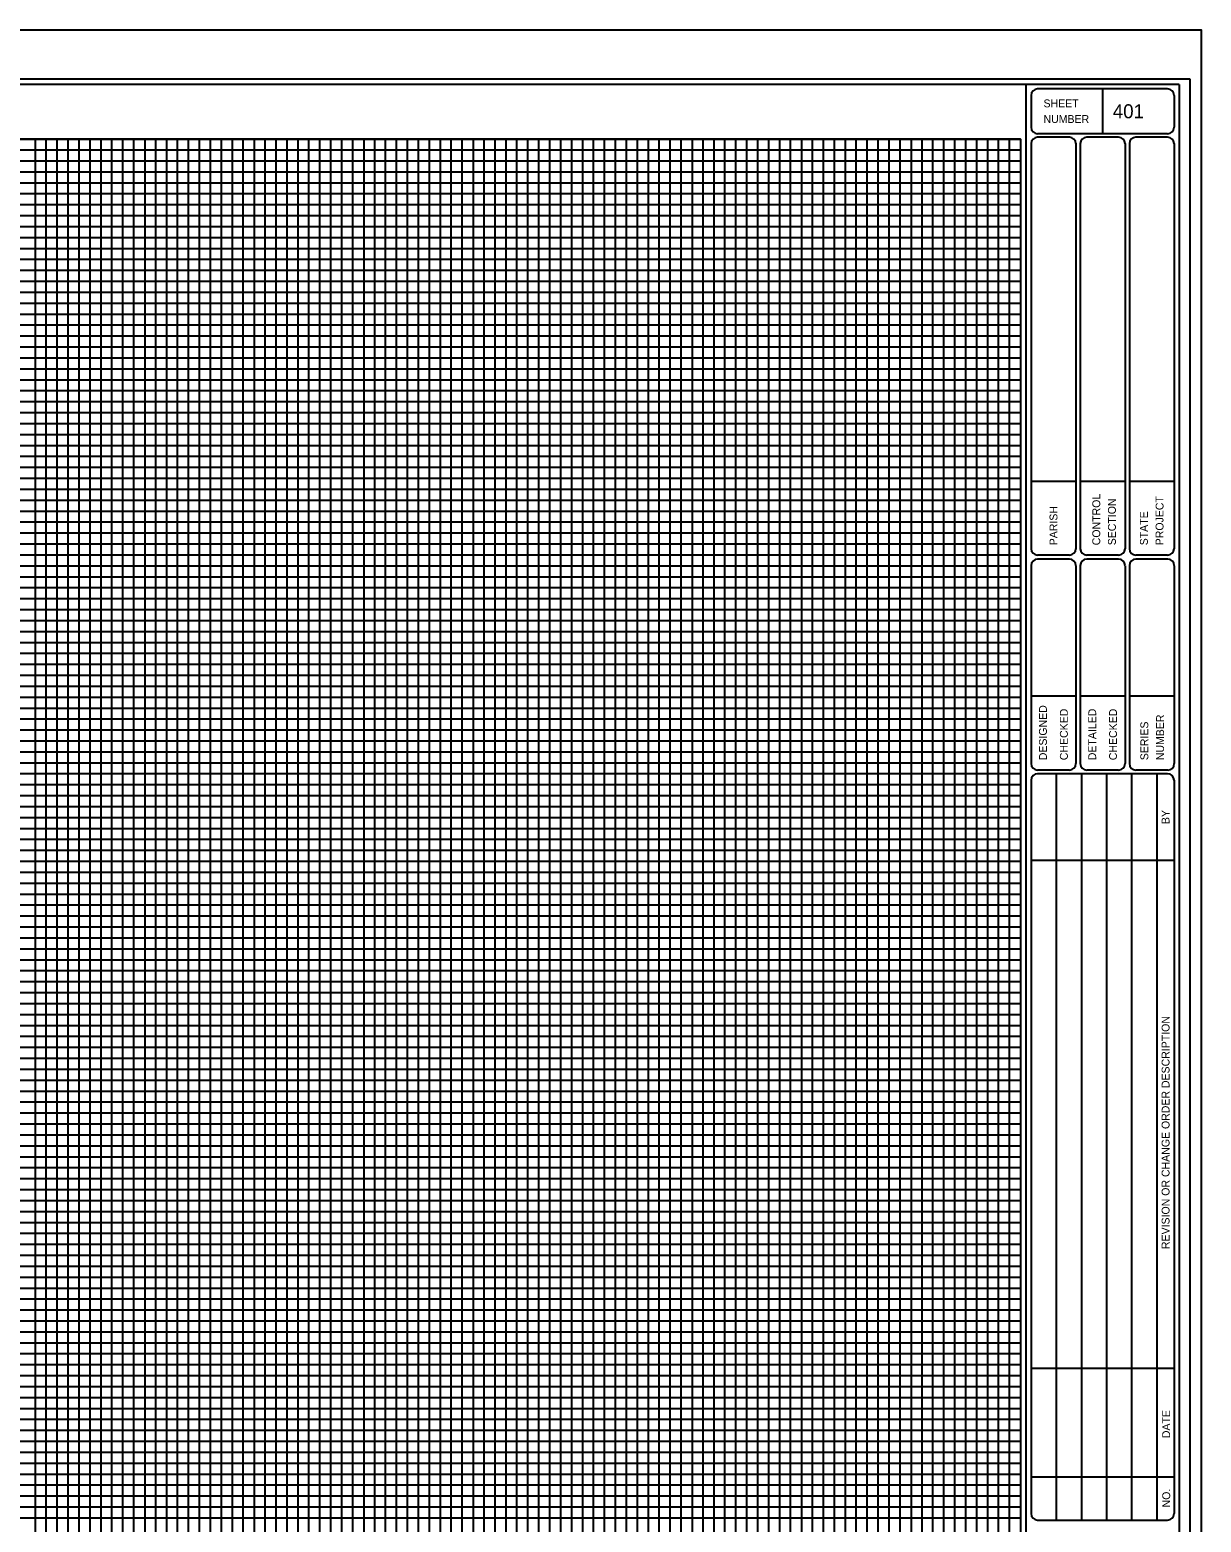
# Model space of a CAD drawing. Extents: x -139 to 18809, y -75 to 270.
# Drawn here: x 233 to 340, y 83.6 to 220 of the extents above; entities that cross this region are included whole.
import ezdxf

# ---------------------------------------------------------------- set-up
doc = ezdxf.new("R2010")
doc.units = 0
for name, color, linetype in [('Grid', 7, 'Continuous'), ('Plot Border', 7, 'Continuous'), ('Sheet Border', 7, 'Continuous')]:
    doc.layers.add(name, color=color, linetype=linetype)

msp = doc.modelspace()

# ---------------------------------------------------------------- linework, layer by layer
at = {"layer": 'Grid'}
for p, q in [((323.5, 210), (23.5, 210)), ((323.5, 209), (23.5, 209)), ((233.5, 210), (233.5, 10)), ((234.5, 10), (234.5, 210)), ((235.5, 10), (235.5, 210)), ((236.5, 10), (236.5, 210)), ((237.5, 10), (237.5, 210)), ((238.5, 10), (238.5, 210)), ((239.5, 10), (239.5, 210)), ((240.5, 10), (240.5, 210)), ((241.5, 10), (241.5, 210)), ((242.5, 10), (242.5, 210)), ((243.5, 210), (243.5, 10)), ((244.5, 10), (244.5, 210)), ((245.5, 10), (245.5, 210)), ((246.5, 10), (246.5, 210)), ((247.5, 10), (247.5, 210)), ((248.5, 10), (248.5, 210)), ((249.5, 10), (249.5, 210)), ((250.5, 10), (250.5, 210)), ((251.5, 10), (251.5, 210)), ((252.5, 10), (252.5, 210)), ((253.5, 210), (253.5, 10)), ((254.5, 10), (254.5, 210)), ((255.5, 10), (255.5, 210)), ((256.5, 10), (256.5, 210)), ((257.5, 10), (257.5, 210)), ((258.5, 10), (258.5, 210)), ((259.5, 10), (259.5, 210)), ((260.5, 10), (260.5, 210)), ((261.5, 10), (261.5, 210)), ((262.5, 10), (262.5, 210)), ((263.5, 210), (263.5, 10)), ((264.5, 10), (264.5, 210)), ((265.5, 10), (265.5, 210)), ((266.5, 10), (266.5, 210)), ((267.5, 10), (267.5, 210)), ((268.5, 10), (268.5, 210)), ((269.5, 10), (269.5, 210)), ((270.5, 10), (270.5, 210)), ((271.5, 10), (271.5, 210)), ((272.5, 10), (272.5, 210)), ((273.5, 210), (273.5, 10)), ((274.5, 10), (274.5, 210)), ((275.5, 10), (275.5, 210)), ((276.5, 10), (276.5, 210)), ((277.5, 10), (277.5, 210)), ((278.5, 10), (278.5, 210)), ((279.5, 10), (279.5, 210)), ((280.5, 10), (280.5, 210)), ((281.5, 10), (281.5, 210)), ((282.5, 10), (282.5, 210)), ((283.5, 210), (283.5, 10)), ((284.5, 10), (284.5, 210)), ((285.5, 10), (285.5, 210)), ((286.5, 10), (286.5, 210)), ((287.5, 10), (287.5, 210)), ((288.5, 10), (288.5, 210)), ((289.5, 10), (289.5, 210)), ((290.5, 10), (290.5, 210)), ((291.5, 10), (291.5, 210)), ((292.5, 10), (292.5, 210)), ((293.5, 210), (293.5, 10)), ((294.5, 10), (294.5, 210)), ((295.5, 10), (295.5, 210)), ((296.5, 10), (296.5, 210)), ((297.5, 10), (297.5, 210)), ((298.5, 10), (298.5, 210)), ((299.5, 10), (299.5, 210)), ((300.5, 10), (300.5, 210)), ((301.5, 10), (301.5, 210)), ((302.5, 10), (302.5, 210)), ((303.5, 210), (303.5, 10)), ((304.5, 10), (304.5, 210)), ((305.5, 10), (305.5, 210)), ((306.5, 10), (306.5, 210)), ((307.5, 10), (307.5, 210)), ((308.5, 10), (308.5, 210)), ((309.5, 10), (309.5, 210)), ((310.5, 10), (310.5, 210)), ((311.5, 10), (311.5, 210)), ((312.5, 10), (312.5, 210)), ((313.5, 210), (313.5, 10)), ((314.5, 10), (314.5, 210)), ((315.5, 10), (315.5, 210)), ((316.5, 10), (316.5, 210)), ((317.5, 10), (317.5, 210)), ((318.5, 10), (318.5, 210)), ((319.5, 10), (319.5, 210)), ((320.5, 10), (320.5, 210)), ((321.5, 10), (321.5, 210)), ((322.5, 10), (322.5, 210)), ((323.5, 208), (23.5, 208)), ((323.5, 207), (23.5, 207)), ((323.5, 206), (23.5, 206)), ((323.5, 205), (23.5, 205)), ((323.5, 204), (23.5, 204)), ((323.5, 203), (23.5, 203)), ((323.5, 202), (23.5, 202)), ((323.5, 201), (23.5, 201)), ((323.5, 200), (23.5, 200)), ((323.5, 199), (23.5, 199)), ((323.5, 198), (23.5, 198)), ((323.5, 197), (23.5, 197)), ((323.5, 196), (23.5, 196)), ((323.5, 195), (23.5, 195)), ((323.5, 194), (23.5, 194)), ((323.5, 193), (23.5, 193)), ((323.5, 192), (23.5, 192)), ((323.5, 191), (23.5, 191)), ((323.5, 190), (23.5, 190)), ((323.5, 189), (23.5, 189)), ((323.5, 188), (23.5, 188)), ((323.5, 187), (23.5, 187)), ((323.5, 186), (23.5, 186)), ((323.5, 185), (23.5, 185)), ((323.5, 184), (23.5, 184)), ((323.5, 183), (23.5, 183)), ((323.5, 182), (23.5, 182)), ((323.5, 181), (23.5, 181)), ((323.5, 180), (23.5, 180)), ((323.5, 179), (23.5, 179)), ((323.5, 178), (23.5, 178)), ((323.5, 177), (23.5, 177)), ((323.5, 176), (23.5, 176)), ((323.5, 175), (23.5, 175)), ((323.5, 174), (23.5, 174)), ((323.5, 173), (23.5, 173)), ((323.5, 172), (23.5, 172)), ((323.5, 171), (23.5, 171)), ((323.5, 170), (23.5, 170)), ((323.5, 169), (23.5, 169)), ((323.5, 168), (23.5, 168)), ((323.5, 167), (23.5, 167)), ((323.5, 166), (23.5, 166)), ((323.5, 165), (23.5, 165)), ((323.5, 164), (23.5, 164)), ((323.5, 163), (23.5, 163)), ((323.5, 162), (23.5, 162)), ((323.5, 161), (23.5, 161)), ((323.5, 160), (23.5, 160)), ((323.5, 159), (23.5, 159)), ((323.5, 158), (23.5, 158)), ((323.5, 157), (23.5, 157)), ((323.5, 156), (23.5, 156)), ((323.5, 155), (23.5, 155)), ((323.5, 154), (23.5, 154)), ((323.5, 153), (23.5, 153)), ((323.5, 152), (23.5, 152)), ((323.5, 151), (23.5, 151)), ((323.5, 150), (23.5, 150)), ((323.5, 149), (23.5, 149)), ((323.5, 148), (23.5, 148)), ((323.5, 147), (23.5, 147)), ((323.5, 146), (23.5, 146)), ((323.5, 145), (23.5, 145)), ((323.5, 144), (23.5, 144)), ((323.5, 143), (23.5, 143)), ((323.5, 142), (23.5, 142)), ((323.5, 141), (23.5, 141)), ((323.5, 140), (23.5, 140)), ((323.5, 139), (23.5, 139)), ((323.5, 138), (23.5, 138)), ((323.5, 137), (23.5, 137)), ((323.5, 136), (23.5, 136)), ((323.5, 135), (23.5, 135)), ((323.5, 134), (23.5, 134)), ((323.5, 133), (23.5, 133)), ((323.5, 132), (23.5, 132)), ((323.5, 131), (23.5, 131)), ((323.5, 130), (23.5, 130)), ((323.5, 129), (23.5, 129)), ((323.5, 128), (23.5, 128)), ((323.5, 127), (23.5, 127)), ((323.5, 126), (23.5, 126)), ((323.5, 125), (23.5, 125)), ((323.5, 124), (23.5, 124)), ((323.5, 123), (23.5, 123)), ((323.5, 122), (23.5, 122)), ((323.5, 121), (23.5, 121)), ((323.5, 120), (23.5, 120)), ((323.5, 119), (23.5, 119)), ((323.5, 118), (23.5, 118)), ((323.5, 117), (23.5, 117)), ((323.5, 116), (23.5, 116)), ((323.5, 115), (23.5, 115)), ((323.5, 114), (23.5, 114)), ((323.5, 113), (23.5, 113)), ((323.5, 112), (23.5, 112)), ((323.5, 111), (23.5, 111)), ((323.5, 110), (23.5, 110)), ((323.5, 109), (23.5, 109)), ((323.5, 108), (23.5, 108)), ((323.5, 107), (23.5, 107)), ((323.5, 106), (23.5, 106)), ((323.5, 105), (23.5, 105)), ((323.5, 104), (23.5, 104)), ((323.5, 103), (23.5, 103)), ((323.5, 102), (23.5, 102)), ((323.5, 101), (23.5, 101)), ((323.5, 100), (23.5, 100)), ((323.5, 99), (23.5, 99)), ((323.5, 98), (23.5, 98)), ((323.5, 97), (23.5, 97)), ((323.5, 96), (23.5, 96)), ((323.5, 95), (23.5, 95)), ((323.5, 94), (23.5, 94)), ((323.5, 93), (23.5, 93)), ((323.5, 92), (23.5, 92)), ((323.5, 91), (23.5, 91)), ((323.5, 90), (23.5, 90)), ((323.5, 89), (23.5, 89)), ((323.5, 88), (23.5, 88)), ((323.5, 87), (23.5, 87)), ((323.5, 86), (23.5, 86)), ((323.5, 85), (23.5, 85)), ((323.5, 84), (23.5, 84))]:
    msp.add_line(p, q, dxfattribs=at)
msp.add_lwpolyline([(23.5, 210), (323.5, 210), (323.5, 10), (23.5, 10)], close=True, dxfattribs=at)
at = {"layer": 'Plot Border'}
for points in [[(0, 220), (340, 220), (340, 0), (0, 0)], [(339, 215.5), (9, 215.5), (9, 4.5), (339, 4.5)]]:
    msp.add_lwpolyline(points, close=True, dxfattribs=at)
at = {"layer": 'Sheet Border'}
for p, q in [((338, 215), (23, 215)), ((324, 215), (324, 5)), ((336.94, 214.6), (325.06, 214.6)), ((331, 214.6), (331, 210.51)), ((338, 215), (338, 5)), ((324.46, 214.01), (324.46, 211.11)), ((337.54, 214.01), (337.54, 211.11)), ((336.94, 210.51), (325.06, 210.51)), ((327.96, 210.2), (325.06, 210.2)), ((332.45, 210.2), (329.54, 210.2)), ((336.94, 210.2), (334.04, 210.2)), ((324.46, 209.64), (324.46, 172.54)), ((328.55, 209.65), (328.55, 172.54)), ((328.95, 209.6), (328.95, 172.59)), ((333.05, 209.61), (333.05, 172.58)), ((333.44, 209.6), (333.44, 172.59)), ((337.54, 209.6), (337.54, 172.59)), ((328.55, 178.73), (324.46, 178.73)), ((333.05, 178.73), (328.95, 178.73)), ((337.54, 178.73), (333.44, 178.73)), ((327.96, 171.99), (325.06, 171.99)), ((332.45, 171.99), (329.54, 171.99)), ((336.94, 171.99), (334.04, 171.99)), ((324.46, 171.08), (324.46, 152.96)), ((327.96, 171.63), (325.06, 171.63)), ((328.56, 171.03), (328.56, 152.96)), ((328.95, 171.08), (328.95, 152.96)), ((332.46, 171.63), (329.55, 171.63)), ((333.05, 171.03), (333.05, 152.96)), ((333.45, 171.08), (333.45, 152.96)), ((336.95, 171.63), (334.04, 171.63)), ((337.54, 171.03), (337.54, 152.96)), ((328.55, 159.1), (324.46, 159.1)), ((333.05, 159.1), (328.95, 159.1)), ((337.54, 159.1), (333.44, 159.1)), ((324.46, 151.43), (324.46, 84.41)), ((327.96, 152.36), (325.06, 152.36)), ((336.94, 152.01), (325.06, 152.01)), ((326.76, 152.01), (326.76, 83.82)), ((329.06, 152.01), (329.06, 83.82)), ((332.46, 152.36), (329.55, 152.36)), ((331.36, 152.01), (331.36, 83.82)), ((333.65, 152.01), (333.65, 83.82)), ((336.95, 152.36), (334.04, 152.36)), ((335.95, 152.01), (335.95, 83.82)), ((337.54, 151.43), (337.54, 84.41)), ((337.54, 144.09), (324.46, 144.09)), ((324.46, 97.69), (337.54, 97.69)), ((324.46, 87.78), (337.54, 87.78)), ((325.06, 83.82), (336.94, 83.82))]:
    msp.add_line(p, q, dxfattribs=at)
for centre, start, end in [((325.06, 214.01), 90, 180), ((336.94, 214.01), 0, 90), ((325.06, 211.1), 180, 270), ((325.06, 209.6), 90, 180), ((327.96, 209.6), 0, 90), ((329.55, 209.6), 90, 180), ((332.45, 209.6), 0, 90), ((334.04, 209.6), 90, 180), ((336.94, 211.1), 270, 0), ((336.94, 209.6), 0, 90), ((325.06, 172.59), 180, 270), ((327.96, 172.59), 270, 0), ((329.55, 172.59), 180, 270), ((332.45, 172.59), 270, 0), ((334.04, 172.59), 180, 270), ((336.94, 172.59), 270, 0), ((325.06, 171.04), 90, 180), ((327.96, 171.04), 0, 90), ((329.55, 171.04), 90, 180), ((332.45, 171.04), 0, 90), ((334.04, 171.04), 90, 180), ((336.95, 171.04), 0, 90), ((325.06, 152.95), 180, 270), ((327.96, 152.95), 270, 0), ((329.55, 152.95), 180, 270), ((332.45, 152.95), 270, 0), ((334.04, 152.95), 180, 270), ((336.95, 152.95), 270, 0), ((325.06, 151.43), 90, 180), ((336.94, 151.43), 0, 90), ((325.06, 84.41), 180, 270), ((336.94, 84.41), 270, 0)]:
    msp.add_arc(centre, 0.594, start, end, dxfattribs=at)

# ---------------------------------------------------------------- texts
for s, height, p in [('SHEET', 0.72, (325.6, 212.92)), (' 401 ', 1.28, (331.45, 211.92)), ('NUMBER', 0.72, (325.6, 211.49))]:
    msp.add_text(s, height=height, dxfattribs=at).set_placement(p)
for s, p in [('CONTROL', (330.78, 172.9)), ('PROJECT', (336.56, 172.9)), ('PARISH', (326.87, 172.9)), ('SECTION', (332.21, 172.9)), ('STATE', (335.13, 172.9)), ('DESIGNED', (325.91, 153.26)), ('CHECKED', (327.82, 153.26)), ('DETAILED', (330.41, 153.26)), ('CHECKED', (332.31, 153.26)), ('NUMBER', (336.61, 153.26)), ('SERIES', (335.17, 153.26)), ('BY', (337.11, 147.42)), ('REVISION OR CHANGE ORDER DESCRIPTION', (337.11, 108.59)), ('DATE', (337.16, 91.31)), ('NO.', (337.17, 84.98))]:
    msp.add_text(s, height=0.72, rotation=90, dxfattribs=at).set_placement(p)

doc.saveas('drawing.dxf')
